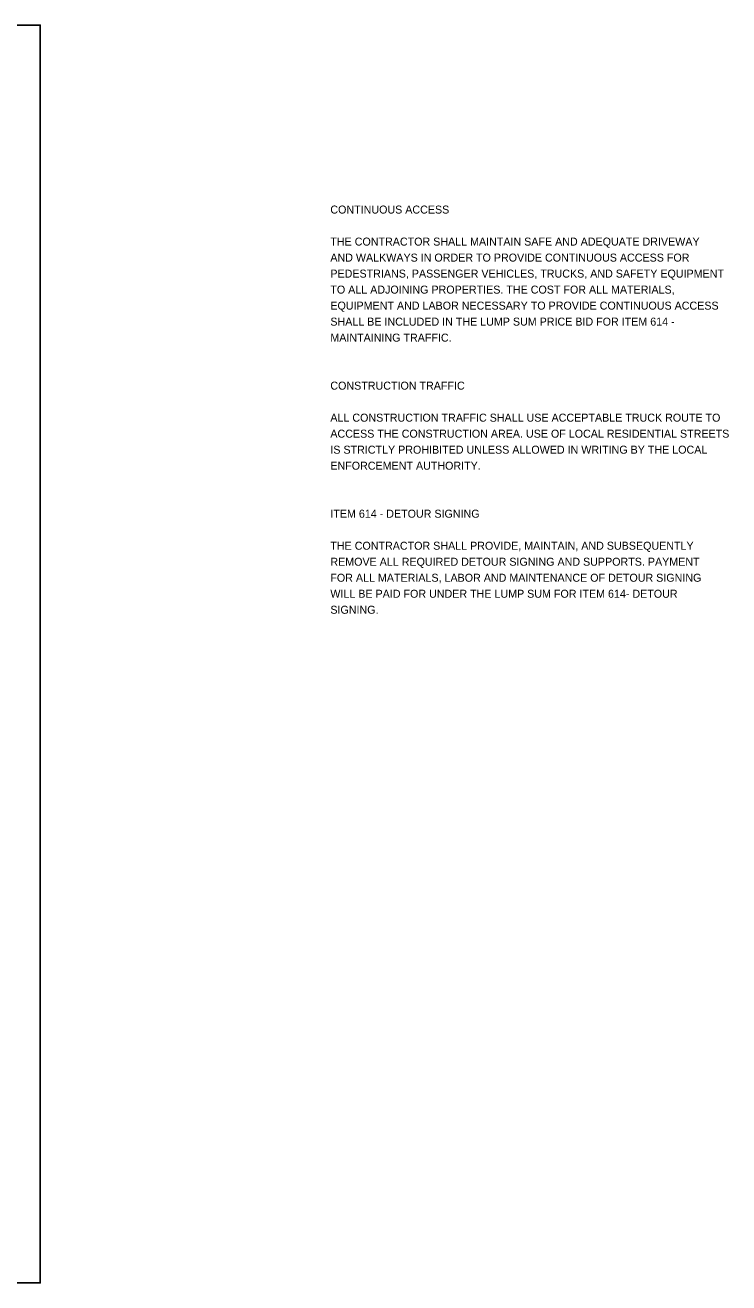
# Model space of a CAD drawing. Extents: x -18.5 to 46, y -14.2 to 42.5.
# Drawn here: x 33.74 to 46.05, y 0 to 22 of the extents above; entities that cross this region are included whole.
import ezdxf

# ---------------------------------------------------------------- set-up
doc = ezdxf.new("R2010")
doc.units = 0
doc.layers.add('SH_Cut_Line', color=7, linetype='Continuous')
doc.layers.add('SH_Text', color=7, linetype='Continuous')

msp = doc.modelspace()

# ---------------------------------------------------------------- linework, layer by layer
at = {"layer": 'SH_Cut_Line'}
msp.add_lwpolyline([(0, 0), (34, 0), (34, 22), (0, 22)], close=True, dxfattribs=at)

# ---------------------------------------------------------------- texts
at = {"layer": 'SH_Text'}
for s, p in [('CONTINUOUS ACCESS', (39.075, 18.704)), ('THE CONTRACTOR SHALL MAINTAIN SAFE AND ADEQUATE DRIVEWAY ', (39.075, 18.144)), ('AND WALKWAYS IN ORDER TO PROVIDE CONTINUOUS ACCESS FOR ', (39.075, 17.864)), ('PEDESTRIANS, PASSENGER VEHICLES, TRUCKS, AND SAFETY EQUIPMENT ', (39.075, 17.584)), ('TO ALL ADJOINING PROPERTIES. THE COST FOR ALL MATERIALS, ', (39.075, 17.304)), ('EQUIPMENT AND LABOR NECESSARY TO PROVIDE CONTINUOUS ACCESS ', (39.075, 17.024)), ('SHALL BE INCLUDED IN THE LUMP SUM PRICE BID FOR ITEM 614 -', (39.075, 16.744)), ('MAINTAINING TRAFFIC.', (39.075, 16.464)), ('CONSTRUCTION TRAFFIC', (39.075, 15.624)), ('ALL CONSTRUCTION TRAFFIC SHALL USE ACCEPTABLE TRUCK ROUTE TO ', (39.075, 15.064)), ('ACCESS THE CONSTRUCTION AREA. USE OF LOCAL RESIDENTIAL STREETS ', (39.075, 14.784)), ('IS STRICTLY PROHIBITED UNLESS ALLOWED IN WRITING BY THE LOCAL ', (39.075, 14.504)), ('ENFORCEMENT AUTHORITY.', (39.075, 14.224)), ('ITEM 614 - DETOUR SIGNING', (39.075, 13.384)), ('THE CONTRACTOR SHALL PROVIDE, MAINTAIN, AND SUBSEQUENTLY ', (39.075, 12.824)), ('REMOVE ALL REQUIRED DETOUR SIGNING AND SUPPORTS. PAYMENT ', (39.075, 12.544)), ('FOR ALL MATERIALS, LABOR AND MAINTENANCE OF DETOUR SIGNING ', (39.075, 12.264)), ('WILL BE PAID FOR UNDER THE LUMP SUM FOR ITEM 614- DETOUR ', (39.075, 11.984)), ('SIGNING.', (39.075, 11.704))]:
    msp.add_text(s, height=0.14, dxfattribs=at).set_placement(p)

doc.saveas('drawing.dxf')
